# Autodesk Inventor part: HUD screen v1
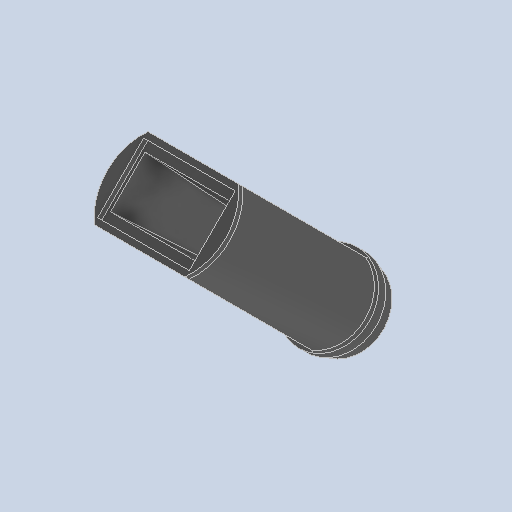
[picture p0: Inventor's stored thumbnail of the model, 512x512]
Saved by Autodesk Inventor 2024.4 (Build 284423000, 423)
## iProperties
Created: 2025-04
Part Number: HUD screen v1
Material: Generic
Document SubType Name: Modeling
Designer: AdminForWorker
Density: 1 g/cm^3
Appearance: Default
Title: HUD screen v1 v2
Author: AdminForWorker
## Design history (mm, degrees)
feature "Body1"
body "Solid1"
